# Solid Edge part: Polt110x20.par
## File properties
Author: Türk
Template: Iso Part.par
Last saved by: Türk
Revision: 13
Application: Solid Edge
Accuracy: 0,990
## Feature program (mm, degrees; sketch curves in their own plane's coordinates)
thread "unnamed Thread 1"
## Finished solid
Body 1: solid body, 23 faces, 45 edges, 24 vertices.
  Faces by surface: plane 21, cylinder 2
  Edges by curve: line 42, circle 3
Bounding box of the edges (mm): 24.000 x 119.500 x 27.713, from (-12, -10, -13.8564) to (12, 109.5, 13.8564).
Cylindrical faces by radius (mm): R10 x2
Planar faces by outward normal: +x 1, +y 2, -x 1, -y 1, oblique 16
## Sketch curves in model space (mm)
circle centre (0, 0, 0) radius 13.8564
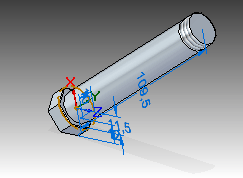
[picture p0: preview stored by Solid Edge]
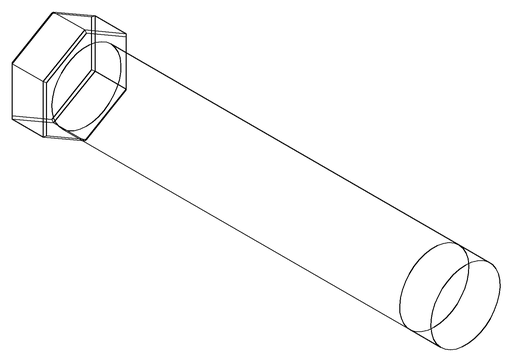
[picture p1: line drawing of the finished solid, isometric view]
